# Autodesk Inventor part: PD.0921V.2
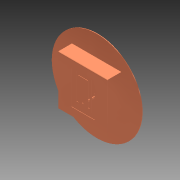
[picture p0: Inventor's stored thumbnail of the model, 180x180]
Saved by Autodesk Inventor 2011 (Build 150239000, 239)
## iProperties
Created: 2014-06
Part Number: PD.0921V.2
Document SubType Name: Modeling
Designer: Evgeny
Density: 1 g/cm^3
Author: Evgeny
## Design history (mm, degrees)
sketch "Эскиз1"
  geometry: L1 (-41, 41)-(41, 41); L2 (41, 41)-(41, -41); L3 (41, -41)-(-41, -41); L4 (-41, -41)-(-41, 41); L5 (19.5, 28)-(19.5, -28); L6 (19.5, -28)-(-19.5, -28); L7 (-19.5, -28)-(-19.5, 28); L8 (14.5, 28)-(14.5, -20); L9 (14.5, -20)-(-14.5, -20); L10 (-14.5, -20)-(-14.5, 28); L11 (-19.5, 28)-(-14.5, 28); L12 (14.5, 28)-(19.5, 28); L13 (-11, 28)-(11, 28); L14 (11, 28)-(11, -16); L15 (-11, -16)-(-11, 28); L16 (-8, -16)-(-8, 23); L17 (-8, 23)-(8, 23); L18 (8, 23)-(8, -16); L19 (11, -16)-(8, -16); L20 (-8, -16)-(-11, -16); C1 r 1.35 at (0, -14); 1 further point
  constraints: 40 end point, 10 parallel, 4 horizontal, 4 perpendicular, 3 collinear, 1 centre point
  dimensions: "d0" = 82 distance between parallel lines of L3 L1; "d1" = 82 distance between parallel lines of L2 L4; "d2" = 41 distance from line of L4 point (0, 0); "d3" = 41 distance from line of L3 point (0, 0); "d4" = 5 distance between parallel lines of L10 L7; "d5" = 5 distance between parallel lines of L5 L8; "d6" = 8 distance between parallel lines of L6 L9; "d7" = 56 distance between parallel lines of L12 L6; "d8" = 28 distance from line of point (0, 0) L6; "d9" = 39 distance between parallel lines of L5 L7; "d10" = 19.5 distance from line of L7 point (0, 0); "d11" = 3 distance between parallel lines of L16 L15; "d12" = 3 distance between parallel lines of L18 L14; "d13" = 5 distance between parallel lines of L13 L17; "d15" = 22 distance between parallel lines of L14 L15; "d16" = 11 distance from line of point (0, 0) L15; "d19" = 2.7 diameter of C1; "d32" = 27 distance from line of L3 C1.centre; "d33" = 16 distance from line of L20 point (0, 0)
extrude "Выдавливание2" new body sketch "Эскиз1" distance "d21" = 0.5; taper "d22" = 0 deg
extrude "Выдавливание3" join sketch "Эскиз1" distance "d23" = 1.5; taper "d25" = 0 deg; dims "d24" = 22.5, "d26" = 0
sketch "Эскиз2"
  geometry: L1 (41, -41)-(41, 41) reference; L2 (-41, 41)-(41, 41); L3 (41, 41)-(41, 40.5); L4 (41, 40.5)-(-41, 40.5); L5 (-41, 40.5)-(-41, 41); 1 further point
  constraints: 8 end point, 2 parallel, 1 horizontal, 1 perpendicular, 1 point on line
  dimensions: "d27" = 0.5 distance between parallel lines of L4 L2
extrude "Выдавливание4" join sketch "Эскиз2" distance "d28" = 22; taper "d29" = 0 deg
fillet "Сопряжение1" dims "d30" = 1.5
fillet "Сопряжение2" dims "d31" = 1
sketch "Эскиз3"
  geometry: C1 r 1.35 at (0, 0) reference; C2 r 4.5 at (0, 0); C3 r 75 at (0, 14); 1 further point
  constraints: 2 centre point, 1 coincident
  dimensions: "d34" = 9 diameter of C2; "d36" = 150 diameter of C3; "d37" = 14 distance of point (0, 14) C1.centre (derived)
extrude "Выдавливание5" join sketch "Эскиз3" distance "d38" = 1; taper "d39" = 0 deg
node "Твердое тело2"
